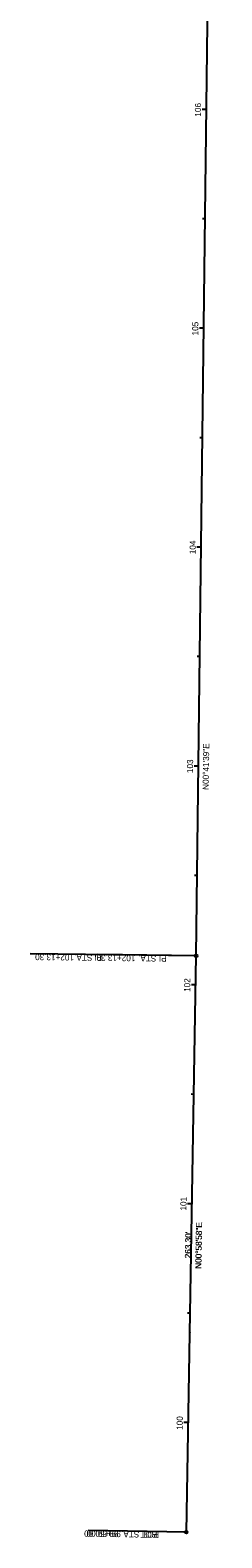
# Model space of a CAD drawing. Extents: x 1652464 to 1652574, y 605963 to 608691.
# Drawn here: x 1652464 to 1652552, y 605963 to 606652 of the extents above; entities that cross this region are included whole.
import ezdxf

# ---------------------------------------------------------------- set-up
doc = ezdxf.new("R2010")
doc.units = 0
for name, color, linetype in [('BR_X_SV_Abut', 7, 'Continuous'), ('Default', 7, 'Continuous'), ('DR_X_Erosion_Control', 7, 'Continuous'), ('DV_X_Property_Line', 7, 'Continuous'), ('DV_X_Section_VMS_Line', 7, 'Continuous'), ('DV_X_Text', 7, 'Continuous'), ('PV_X_Curb', 7, 'Continuous'), ('RW_X_Fee_RW', 7, 'Continuous'), ('RW_X_Occupied_Area', 7, 'Continuous'), ('VG_X_Flower_Bed', 7, 'Continuous'), ('VG_X_Shrub_Line_Lt', 7, 'Continuous')]:
    doc.layers.add(name, color=color, linetype=linetype)

msp = doc.modelspace()

# ---------------------------------------------------------------- linework, layer by layer
at = {"layer": 'Default'}
for p, q in [((1652536.99, 606053.42), (1652536.98, 606052.81)), ((1652537.06, 606057.13), (1652537.05, 606056.93))]:
    msp.add_line(p, q, dxfattribs=at)
at = {"layer": 'DV_X_Section_VMS_Line'}
for p, q in [((1652544.69, 606615.73), (1652542.69, 606615.75)), ((1652544.08, 606565.73), (1652542.88, 606565.75)), ((1652543.48, 606515.74), (1652541.48, 606515.76)), ((1652542.87, 606465.74), (1652541.67, 606465.75)), ((1652542.27, 606415.74), (1652540.27, 606415.77)), ((1652541.66, 606365.75), (1652540.46, 606365.76)), ((1652541.06, 606315.75), (1652539.06, 606315.77)), ((1652540.45, 606265.75), (1652539.25, 606265.77)), ((1652539.78, 606215.76), (1652537.78, 606215.79)), ((1652538.92, 606165.77), (1652537.72, 606165.79)), ((1652538.06, 606115.77), (1652536.06, 606115.81)), ((1652537.2, 606065.78), (1652536.01, 606065.8)), ((1652536.35, 606015.79), (1652534.35, 606015.82)), ((1652535.49, 605965.8), (1652534.29, 605965.82))]:
    msp.add_line(p, q, dxfattribs=at)
at = {"layer": 'DV_X_Text'}
for p, q in [((1652540.01, 606229.06), (1652463.93, 606229.98)), ((1652540.01, 606229.06), (1652495.01, 606229.6)), ((1652535.49, 605965.8), (1652490.5, 605966.57))]:
    msp.add_line(p, q, dxfattribs=at)
for centre in [(1652540.01, 606229.06), (1652540.01, 606229.06), (1652535.49, 605965.8)]:
    msp.add_circle(centre, 0.6, dxfattribs=at)
at = {"layer": 'PV_X_Curb'}
for p, q in [((1652540.01, 606229.06), (1652551.76, 607199.34)), ((1652535.49, 605965.8), (1652540.01, 606229.06))]:
    msp.add_line(p, q, dxfattribs=at)
at = {"layer": 'RW_X_Occupied_Area'}
for p, q in [((1652540.01, 606229.06), (1652551.76, 607199.34)), ((1652540.01, 606229.06), (1652551.76, 607199.34)), ((1652535.49, 605965.8), (1652540.01, 606229.06)), ((1652535.49, 605965.8), (1652540.01, 606229.06))]:
    msp.add_line(p, q, dxfattribs=at)
at = {"layer": 'VG_X_Flower_Bed'}
for p, q in [((1652540.01, 606229.06), (1652495.01, 606229.6)), ((1652535.49, 605965.8), (1652490.5, 605966.57))]:
    msp.add_line(p, q, dxfattribs=at)
for centre in [(1652540.01, 606229.06), (1652535.49, 605965.8)]:
    msp.add_circle(centre, 0.6, dxfattribs=at)
at = {"layer": 'VG_X_Shrub_Line_Lt'}
for p, q in [((1652544.69, 606615.73), (1652543.49, 606615.74)), ((1652543.48, 606515.74), (1652541.48, 606515.76)), ((1652542.27, 606415.74), (1652541.07, 606415.76)), ((1652541.06, 606315.75), (1652539.86, 606315.76)), ((1652539.78, 606215.76), (1652538.58, 606215.78)), ((1652538.06, 606115.77), (1652536.86, 606115.79)), ((1652536.35, 606015.79), (1652534.35, 606015.82))]:
    msp.add_line(p, q, dxfattribs=at)

# ---------------------------------------------------------------- texts
at = {"layer": 'BR_X_SV_Abut'}
msp.add_text('N00°58\'58"E', height=2.8, rotation=89.01726, dxfattribs=at).set_placement((1652542.36, 606086.17))
at = {"layer": 'DR_X_Erosion_Control'}
msp.add_text("263.30'", height=2.8, rotation=89.01726, dxfattribs=at).set_placement((1652537.59, 606090.94))
at = {"layer": 'DV_X_Property_Line'}
for s, rotation, p in [('N00°41\'39"E', 89.30592, (1652545.72, 606304.86)), ('N00°58\'58"E', 89.01726, (1652542.35, 606085.98))]:
    msp.add_text(s, height=2.8, rotation=rotation, dxfattribs=at).set_placement(p)
at = {"layer": 'DV_X_Section_VMS_Line'}
for s, rotation, p in [('106', 89.30592, (1652542.15, 606612.4)), ('105', 89.30592, (1652540.94, 606512.46)), ('104', 89.30592, (1652539.73, 606412.5)), ('103', 89.30592, (1652538.52, 606312.51)), ('102', 89.01726, (1652537.22, 606212.52)), ('101', 89.01726, (1652535.51, 606112.67)), ('100', 89.01726, (1652533.79, 606012.48))]:
    msp.add_text(s, height=2.8, rotation=rotation, dxfattribs=at).set_placement(p)
at = {"layer": 'DV_X_Text'}
for s, rotation, p in [('102+13.30', 179.30592, (1652484.05, 606229.69)), (' STA. ', 179.30592, (1652493.5, 606229.58)), ('PI', 179.30592, (1652496.89, 606229.54)), ('99+50.00', 179.01726, (1652505.52, 605966.27)), (' STA. ', 179.01726, (1652514.97, 605966.11)), ('POT', 179.01726, (1652522.17, 605965.98))]:
    msp.add_text(s, height=2.8, rotation=rotation, dxfattribs=at).set_placement(p)
at = {"layer": 'RW_X_Fee_RW'}
msp.add_text("263.30'", height=2.8, rotation=89.01726, dxfattribs=at).set_placement((1652537.59, 606090.75))
at = {"layer": 'VG_X_Flower_Bed'}
for s, rotation, p in [('102+13.30', 179.30592, (1652512.18, 606229.35)), (' STA. ', 179.30592, (1652522.76, 606229.22)), ('PI', 179.30592, (1652526.46, 606229.18)), ('99+50.00', 179.01726, (1652504.41, 605966.28)), (' STA. ', 179.01726, (1652514.99, 605966.1)), ('POT', 179.01726, (1652523.03, 605965.96))]:
    msp.add_text(s, height=2.8, rotation=rotation, dxfattribs=at).set_placement(p)
at = {"layer": 'VG_X_Shrub_Line_Lt'}
for s, rotation, p in [('105', 89.30592, (1652540.9, 606512.46)), ('100', 89.01726, (1652533.75, 606012.49))]:
    msp.add_text(s, height=2.8, rotation=rotation, dxfattribs=at).set_placement(p)

doc.saveas('drawing.dxf')
